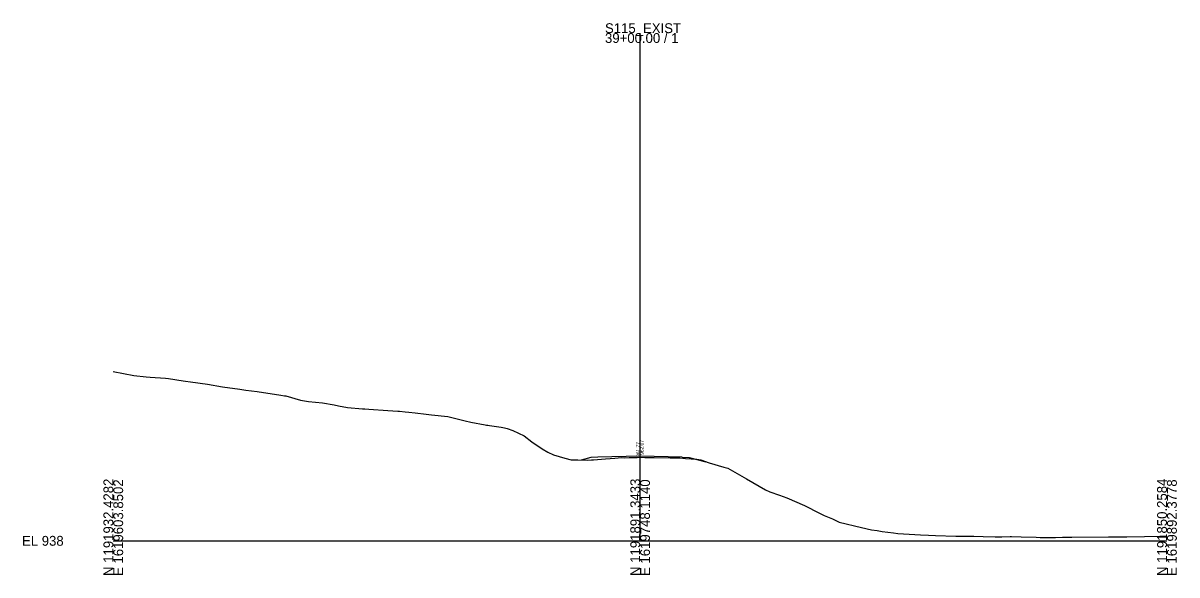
# Model space of a CAD drawing. Extents: x 1620351 to 1620680, y 1192592 to 1195749.
# Drawn here: x 1620351.1 to 1620679.6, y 1195591.8 to 1195748.8 of the extents above; entities that cross this region are included whole.
import ezdxf

# ---------------------------------------------------------------- set-up
doc = ezdxf.new("R2010")
doc.units = 0
for name, color, linetype in [('RD_GPK_XS_Cell', 7, 'Continuous'), ('RD_XS_EarthShd', 7, 'Continuous'), ('RD_XS_ExGround', 7, 'Continuous'), ('RD_XS_Pave', 7, 'Continuous'), ('RD_XS_TieSlope', 7, 'Continuous'), ('RD_XS_TX_Elev_EX', 7, 'Continuous'), ('RD_XS_TX_Elev_PR', 7, 'Continuous')]:
    doc.layers.add(name, color=color, linetype=linetype)

msp = doc.modelspace()

# ---------------------------------------------------------------- linework, layer by layer
at = {"layer": 'RD_GPK_XS_Cell'}
for p, q in [((1620526.76, 1195601.47), (1620526.76, 1195745.92)), ((1620376.76, 1195601.47), (1620526.76, 1195601.47)), ((1620526.76, 1195601.47), (1620676.76, 1195601.47))]:
    msp.add_line(p, q, dxfattribs=at)
at = {"layer": 'RD_XS_EarthShd'}
for p, q in [((1620514.76, 1195625.3), (1620512.76, 1195625.14)), ((1620538.76, 1195625.3), (1620540.76, 1195625.14))]:
    msp.add_line(p, q, dxfattribs=at)
at = {"layer": 'RD_XS_ExGround'}
msp.add_lwpolyline([(1620376.76, 1195649.62), (1620382.61, 1195648.54), (1620386.07, 1195648.16), (1620387.28, 1195648.04), (1620391.61, 1195647.75), (1620392.52, 1195647.63), (1620396.68, 1195646.94), (1620397.32, 1195646.86), (1620398.7, 1195646.67), (1620403.58, 1195646.06), (1620407.89, 1195645.29), (1620412.79, 1195644.66), (1620414.48, 1195644.34), (1620417.7, 1195643.99), (1620424.47, 1195642.94), (1620425.5, 1195642.75), (1620425.88, 1195642.72), (1620430.02, 1195641.49), (1620432.37, 1195641.11), (1620436.35, 1195640.7), (1620439.64, 1195640.14), (1620440.91, 1195639.86), (1620443.45, 1195639.36), (1620447.71, 1195639.06), (1620448.37, 1195639.01), (1620449.5, 1195638.9), (1620454.94, 1195638.55), (1620457.77, 1195638.33), (1620458.25, 1195638.32), (1620459.86, 1195638.16), (1620460.91, 1195638.06), (1620462.7, 1195637.9), (1620465.84, 1195637.55), (1620467.35, 1195637.35), (1620472.01, 1195636.82), (1620472.79, 1195636.68), (1620476.99, 1195635.58), (1620478.57, 1195635.27), (1620482.65, 1195634.46), (1620483.05, 1195634.4), (1620483.44, 1195634.33), (1620483.9, 1195634.25), (1620487.21, 1195633.85), (1620488.14, 1195633.6), (1620488.91, 1195633.39), (1620490.51, 1195632.88), (1620493.72, 1195631.38), (1620495.96, 1195629.59), (1620498.87, 1195627.65), (1620500.47, 1195626.65), (1620502.13, 1195625.95), (1620505.31, 1195624.94), (1620507.12, 1195624.53), (1620509.04, 1195624.48), (1620511.85, 1195624.4), (1620512.92, 1195624.49), (1620513.49, 1195624.53), (1620516.87, 1195624.78), (1620519.54, 1195624.99), (1620521.43, 1195625.14), (1620522.37, 1195625.1), (1620523.65, 1195625.13), (1620525.91, 1195625.22), (1620526.76, 1195625.24), (1620528.08, 1195625.19), (1620530.8, 1195625.14), (1620535.28, 1195625.1), (1620538.06, 1195625.05), (1620539.72, 1195624.92), (1620542.86, 1195624.69), (1620544.08, 1195624.47), (1620546.42, 1195623.62), (1620550.59, 1195622.4), (1620551.75, 1195622.11), (1620557, 1195619.09), (1620562.43, 1195616.01), (1620563.72, 1195615.39), (1620566.42, 1195614.49), (1620568.51, 1195613.66), (1620573.55, 1195611.55), (1620577.85, 1195609.35), (1620579.13, 1195608.65), (1620581.57, 1195607.74), (1620583.44, 1195606.74), (1620589.78, 1195605.3), (1620592.62, 1195604.62), (1620594.25, 1195604.41), (1620595.69, 1195604.16), (1620598.92, 1195603.71), (1620600.16, 1195603.59), (1620606.59, 1195603.19), (1620608.82, 1195603.04), (1620610.85, 1195603.03), (1620616.61, 1195602.78), (1620619.54, 1195602.75), (1620621.74, 1195602.81), (1620624.42, 1195602.74), (1620627.85, 1195602.63), (1620629.75, 1195602.65), (1620632.09, 1195602.71), (1620632.52, 1195602.69), (1620635.21, 1195602.61), (1620639.53, 1195602.51), (1620640.63, 1195602.46), (1620643.38, 1195602.4), (1620645.06, 1195602.39), (1620647.04, 1195602.49), (1620648.57, 1195602.51), (1620649.64, 1195602.55), (1620660.14, 1195602.62), (1620661.54, 1195602.63), (1620663.92, 1195602.58), (1620665.37, 1195602.62), (1620670.4, 1195602.72), (1620674.78, 1195602.81), (1620676.76, 1195602.79)], dxfattribs=at)
at = {"layer": 'RD_XS_Pave'}
for p, q in [((1620526.76, 1195625.54), (1620514.76, 1195625.3)), ((1620538.76, 1195625.3), (1620526.76, 1195625.54))]:
    msp.add_line(p, q, dxfattribs=at)
at = {"layer": 'RD_XS_TieSlope'}
for p, q in [((1620512.76, 1195625.14), (1620510, 1195624.45)), ((1620540.76, 1195625.14), (1620545.49, 1195623.96))]:
    msp.add_line(p, q, dxfattribs=at)

# ---------------------------------------------------------------- texts
at = {"layer": 'RD_GPK_XS_Cell'}
for s, p in [('S115_EXIST', (1620516.76, 1195745.92)), ('39+00.00 / 1', (1620516.76, 1195743.12)), ('EL 938', (1620350.76, 1195600.07))]:
    msp.add_text(s, height=2.8, dxfattribs=at).set_placement(p)
for s, p in [('N 1191932.4282', (1620376.76, 1195591.47)), ('N 1191891.3433', (1620526.76, 1195591.47)), ('N 1191850.2584', (1620676.76, 1195591.47)), ('E 1619603.8502', (1620379.56, 1195591.47)), ('E 1619748.1140', (1620529.56, 1195591.47)), ('E 1619892.3778', (1620679.56, 1195591.47))]:
    msp.add_text(s, height=2.8, rotation=90, dxfattribs=at).set_placement(p)
at = {"layer": 'RD_XS_TX_Elev_EX'}
msp.add_text('961.77', height=1, rotation=90, dxfattribs=at).set_placement((1620526.66, 1195625.34))
at = {"layer": 'RD_XS_TX_Elev_PR'}
msp.add_text(' 962.07', height=1, rotation=90, dxfattribs=at).set_placement((1620527.76, 1195625.54))

doc.saveas('drawing.dxf')
